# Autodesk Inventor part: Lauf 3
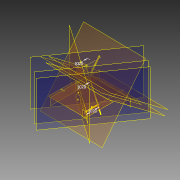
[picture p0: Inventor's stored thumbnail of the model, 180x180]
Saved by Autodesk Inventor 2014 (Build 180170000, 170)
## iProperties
Created: 2013-09
Part Number: Lauf 3
Material: Edelstahl
Document SubType Name: Modeling
Designer: Stefan Tammegger
Mass: 12281.6 g
Surface Area: 15206.1 cm^2
Volume: 1520 cm^3
Density: 8.08 g/cm^3
Appearance: Halbpoliert
Author: Stefan Tammegger
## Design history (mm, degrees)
workplane "Arbeitsebene1"
workplane "Arbeitsebene2"
workplane "Arbeitsebene5"
  workaxis "Arbeitsachse3"
workplane "Arbeitsebene6"
sketch "Skizze2"
  geometry: L1 (1555.396, -769.838)-(1555.396, -948.838) reference; L2 (1272.396, -769.838)-(1555.396, -769.838) reference; L3 (1555.396, -769.838)-(1555.396, 250.162); 2 further points
  constraints: 2 end point, 1 coincident, 1 perpendicular
  dimensions: "d11" = 1020 distance of L1.start L3.end
  node "Referenz2"
  node "Referenz3"
sketch "Skizze3"
  geometry: L1 (70, -835.546)-(120, -835.546); L2 (120, -835.546)-(120, -805.546); L3 (120, -805.546)-(70, -805.546); L4 (70, -805.546)-(70, -835.546); L5 (118, -833.546)-(72, -833.546); L6 (72, -833.546)-(72, -807.546); L7 (72, -807.546)-(118, -807.546); L8 (118, -807.546)-(118, -833.546); L9 (0, 0)-(0, 146.63) reference; L10 (-2841.447, 0)-(2048.984, 0) reference; 2 further points
  constraints: 16 end point, 4 parallel, 2 perpendicular, 1 horizontal, 3 other
  dimensions: "d12" = 50 distance of L1.start L1.end; "d13" = 30 distance of L1.end L2.end; "d14" = 2 distance between parallel lines of L3 L7; "d15" = 70 distance between parallel lines of L9 L4; "d16" = 0 distance from line of L1 point (0, -835.546)
extrude "Extrusion1" new body sketch "Skizze3" distance "d17" = 5000; taper "d18" = 0 deg
workplane "Arbeitsebene8"
sketch "Skizze4"
  geometry: L1 (-1045.237, -70)-(3050.576, -70) reference; L2 (-1045.237, -120)-(3050.576, -120) reference; L3 (-283, 0)-(-283, -500) reference; L4 (0, 0)-(0, -500) reference; L5 (-200, -55)-(-90, -55); L6 (-90, -55)-(-90, -135); L7 (-90, -135)-(-200, -135); L8 (-200, -135)-(-200, -55); C1 r 5.5 at (-185, -95); C2 r 5.5 at (-105, -95); 1 further point
  constraints: 8 end point, 2 centre point, 2 parallel, 1 horizontal, 1 perpendicular
  dimensions: "d19" = 110 distance of L6.end L7.end; "d20" = 80 distance of L7.end L5.start; "d21" = 90 distance between parallel lines of L4 L6; "d22" = 15 distance between parallel lines of L2 L7; "d23" = 11 diameter of C1; "d24" = 11 diameter of C2; "d25" = 15 distance from line of L8 C1.centre; "d26" = 15 distance from line of L6 C2.centre; "d27" = 40 distance from line of L7 C1.centre; "d28" = 40 distance from line of L7 C2.centre
extrude "Extrusion2" new body sketch "Skizze4" distance "d29" = 6; taper "d30" = 0 deg
fillet "Rundung1" dims "d31" = 4
sketch "Skizze5"
  geometry: L1 (90, 131)-(90, 59) reference; L2 (94, 55)-(196, 55) reference; L3 (130, 120)-(160, 120); L4 (160, 120)-(160, 70); L5 (160, 70)-(130, 70); L6 (130, 70)-(130, 120); L7 (158, 118)-(132, 118); L8 (132, 118)-(132, 72); L9 (132, 72)-(158, 72); L10 (158, 72)-(158, 118); 1 further point
  constraints: 16 end point, 4 parallel, 2 perpendicular, 1 horizontal, 3 other
  dimensions: "d32" = 50 distance of L3.end L4.end; "d33" = 30 distance of L3.start L3.end; "d34" = 40 distance between parallel lines of L1 L6; "d35" = 15 distance between parallel lines of L2 L5; "d36" = 2 distance between parallel lines of L6 L8
extrude "Extrusion3" new body sketch "Skizze5" distance "d37" = 1200; taper "d38" = 0 deg
sketch "Skizze6"
  geometry: L1 (5000, -30)-(5000, 0) reference; L2 (5000, 0)-(0, 0) reference; L3 (0, -30)-(0, 0) reference; L4 (5000, -30)-(0, -30) reference; L5 (4561.311, -916.867)-(3873.037, 66.128) reference; L6 (4536.736, -934.074)-(3848.463, 48.922) reference; 3 further points
  constraints: 4 point on line
sketch "Skizze7"
  geometry: L1 (50, 0)-(0, 0) reference; L2 (50, 0)-(50, 1200) reference; L3 (0, 1200)-(50, 1200) reference; L4 (0, 0)-(0, 1200) reference; L5 (0, 499.448)-(50, 499.448) reference; L6 (50, 499.448)-(50, 3367.255) reference; L7 (0, 3367.255)-(50, 3367.255) reference; L8 (0, 499.448)-(0, 3367.255) reference; 2 further points
  constraints: 1 point on line
  node "Projizierte Kontur1"
workplane "Arbeitsebene9"
feature "Trennen1"
feature "Trennen2"
workplane "Arbeitsebene10"
sketch "Skizze8"
  geometry: L1 (0, 0)-(0, -500) reference; L2 (1020, 50.711)-(1020, -500); 1 further point
  constraints: 2 end point, 1 parallel
  dimensions: "d39" = 1020 distance between parallel lines of L1 L2
  node "Referenz7"
workplane "Arbeitsebene13"
  workplane "Arbeitsebene12"
workpoint "Arbeitspunkt1"
workpoint "Arbeitspunkt2"
workplane "Arbeitsebene14"
workpoint "Arbeitspunkt5"
workplane "Arbeitsebene15"
  workpoint "Arbeitspunkt3"
  workpoint "Arbeitspunkt4"
workplane "Arbeitsebene16"
sketch "Skizze11"
  geometry: L1 (0, 0)-(500, 0) reference; L2 (33.807, 1020)-(500, 1020); 1 further point
  constraints: 2 end point, 1 parallel
  dimensions: "d50" = 1020 distance between parallel lines of L1 L2
  node "Referenz8"
workplane "Arbeitsebene17"
  workaxis "Arbeitsachse4"
sketch "Skizze12"
  geometry: L1 (33.807, -831.485)-(500, -831.485) reference; L2 (0, 184.613)-(0, 43.995) reference; L3 (30, -831.485)-(80, -831.485); L4 (80, -831.485)-(80, -801.485); L5 (80, -801.485)-(30, -801.485); L6 (30, -801.485)-(30, -831.485); L7 (32, -803.485)-(78, -803.485); L8 (78, -803.485)-(78, -829.485); L9 (78, -829.485)-(32, -829.485); L10 (32, -829.485)-(32, -803.485); 1 further point
  constraints: 16 end point, 4 parallel, 2 perpendicular, 1 horizontal, 3 other
  dimensions: "d52" = 50 distance of L3.start L3.end; "d53" = 30 distance of L3.end L4.end; "d54" = 0 distance between parallel lines of L1 L3; "d55" = 30 distance between parallel lines of L2 L6; "d56" = 2 distance between parallel lines of L1 L9
extrude "Extrusion5" new body sketch "Skizze12" stored distance "d57" = 2800; taper "d58" = 0 deg
workplane "Arbeitsebene18"
sketch "Skizze13"
  geometry: L1 (17.005, 930.85)-(48.24, -1306.042) reference; L2 (98.235, -1305.344)-(67, 931.548) reference; L3 (-130, -120)-(470, -120) reference; L4 (0, 0)-(448.724, -387.328) reference; L5 (470, -70)-(-130, -70) reference; L6 (81.096, -70)-(-8.904, -70); L7 (-8.904, -70)-(-8.904, -135); L8 (-8.904, -135)-(81.096, -135); L9 (81.096, -135)-(81.096, -70); C1 r 5.5 at (6.096, -102.5); 1 further point
  constraints: 8 end point, 2 parallel, 2 point on line, 1 centre point, 1 horizontal, 1 perpendicular
  dimensions: "d62" = 90 distance of L8.end L7.end; "d63" = 65 distance of L7.end L6.end; "d64" = 11 diameter of C1; "d65" = 15 distance from line of L7 C1.centre; "d66" = 32.5 distance from line of L8 C1.centre
extrude "Extrusion6" new body sketch "Skizze13" distance "d67" = 6; taper "d68" = 0 deg
fillet "Rundung2" dims "d69" = 4
sketch "Skizze14"
  geometry: L1 (-98.235, 1305.344)-(-67, -931.548) reference; L2 (-17.005, -930.85)-(-48.24, 1306.042) reference; L3 (130, 120)-(-470, 120) reference; L4 (-470, 70)-(130, 70) reference; L5 (-31.679, 120)-(-30.98, 70.005); L6 (-30.98, 70.005)-(-80.976, 69.307); L7 (-80.976, 69.307)-(-81.674, 119.302); L8 (-81.674, 119.302)-(-31.679, 120); L9 (-33.65, 117.972)-(-33.008, 71.977); L10 (-33.008, 71.977)-(-79.004, 71.334); L11 (-79.004, 71.334)-(-79.646, 117.33); L12 (-79.646, 117.33)-(-33.65, 117.972); 1 further point
  constraints: 16 end point, 5 point on line, 3 other
  dimensions: "d70" = 50 distance of L5.start L5.end; "d71" = 50 distance of L5.end L6.end; "d72" = 50 distance of L6.end L7.end; "d73" = 2 distance between parallel lines of L8 L12
extrude "Extrusion7" new body sketch "Skizze14" distance "d74" = 1500; taper "d75" = 0 deg
sketch "Skizze15"
  geometry: L1 (0, 0)-(-50, 0) reference; L2 (0, 0)-(0, 1500) reference; L3 (-50, 1500)-(0, 1500) reference; L4 (-50, 0)-(-50, 1500) reference; L5 (-1236.158, 344.407)-(1000.952, 2028.253) reference; L6 (-1218.116, 320.438)-(1018.994, 2004.284) reference; 3 further points
  constraints: 4 point on line
sketch "Skizze16"
  geometry: L1 (0, 0)-(-50, 0) reference; L2 (0, 0)-(0, 1500) reference; L3 (-50, 1500)-(0, 1500) reference; L4 (-50, 0)-(-50, 1500) reference; L5 (-1050.952, 2028.253)-(1186.158, 344.407) reference; 2 further points
  constraints: 2 point on line
workplane "Arbeitsebene19"
feature "Trennen5"
feature "Trennen6"
workplane "Arbeitsebene20"
feature "Trennen7"
workplane "Arbeitsebene21"
sketch "Skizze17"
  geometry: L1 (27.854, 153.926)-(42.527, -896.924) reference; L2 (92.522, -896.226)-(77.849, 154.624) reference; L3 (0, 0)-(499.951, 6.981) reference; L4 (3.63, -259.975)-(0, 0) reference; L5 (15.308, -21.985)-(16.565, -111.976); L6 (16.565, -111.976)-(96.557, -110.859); L7 (96.557, -110.859)-(95.301, -20.868); L8 (95.301, -20.868)-(15.308, -21.985); C1 r 5.5 at (56.352, -96.419); 1 further point
  constraints: 8 end point, 2 parallel, 1 centre point, 1 perpendicular
  dimensions: "d77" = 90 distance of L5.start L5.end; "d78" = 80 distance of L5.end L6.end; "d80" = 90 distance of L6.end L7.end; "d81" = 15 distance between parallel lines of L7 L2; "d82" = 11 diameter of C1; "d83" = 15 distance from line of C1.centre L6; "d84" = 40 distance from line of L5 C1.centre
extrude "Extrusion8" new body sketch "Skizze17" distance "d85" = 6; taper "d86" = 0 deg
sketch "Skizze18"
  geometry: L1 (-95.301, 20.868)-(-15.308, 21.985) reference; L2 (-92.522, 896.226)-(-77.849, -154.624) reference; L3 (-27.854, -153.926)-(-42.527, 896.924) reference; L4 (-80.302, 21.077)-(-30.307, 21.775); L5 (-30.307, 21.775)-(-30.726, 51.772); L6 (-30.726, 51.772)-(-80.721, 51.074); L7 (-80.721, 51.074)-(-80.302, 21.077); L8 (-78.33, 23.105)-(-32.335, 23.747); L9 (-32.335, 23.747)-(-32.698, 49.745); L10 (-32.698, 49.745)-(-78.693, 49.102); L11 (-78.693, 49.102)-(-78.33, 23.105); 1 further point
  constraints: 16 end point, 5 point on line, 2 perpendicular, 3 other
  dimensions: "d87" = 30 distance of L4.end L5.end; "d88" = 50 distance of L5.end L6.end; "d89" = 2 distance between parallel lines of L10 L6
extrude "Extrusion9" new body sketch "Skizze18" distance "d90" = 1500; taper "d91" = 0 deg
sketch "Skizze19"
  geometry: L1 (-1315.388, 30)-(-1275.387, 0) reference; L2 (-1275.387, 0)-(0, 0) reference; L3 (0, 30)-(0, 0) reference; L4 (-1315.388, 30)-(0, 30) reference; L5 (-961.334, -905.121)-(-59.274, 293.331) reference; L6 (-937.365, -923.162)-(-35.305, 275.289) reference; 3 further points
  constraints: 4 point on line
sketch "Skizze20"
  geometry: L1 (1275.387, 0)-(1315.388, 30) reference; L2 (0, 30)-(1315.388, 30) reference; L3 (0, 0)-(0, 30) reference; L4 (1275.387, 0)-(0, 0) reference; L5 (961.334, -905.121)-(59.274, 293.331) reference; 2 further points
  constraints: 2 point on line
workplane "Arbeitsebene22"
feature "Trennen8"
feature "Trennen9"
workplane "Arbeitsebene23"
sketch "Skizze21"
  geometry: L1 (-1561, -70)-(968.98, -70) reference; L2 (-1560.99, -120)-(969.679, -120) reference; L3 (-277, 0)-(-277, -500) reference; L4 (0, 0)-(0, -500) reference; L5 (-190, -55)-(-80, -55); L6 (-80, -55)-(-80, -135); L7 (-80, -135)-(-190, -135); L8 (-190, -135)-(-190, -55); C1 r 5.5 at (-175, -95); C2 r 5.5 at (-95, -95); 1 further point
  constraints: 8 end point, 2 centre point, 2 parallel, 1 horizontal, 1 perpendicular
  dimensions: "d92" = 110 distance of L5.start L5.end; "d93" = 80 distance of L5.end L6.end; "d94" = 15 distance between parallel lines of L1 L5; "d95" = 80 distance between parallel lines of L4 L6; "d96" = 11 diameter of C1; "d97" = 11 diameter of C2; "d98" = 15 distance from line of L8 C1.centre; "d99" = 15 distance from line of L6 C2.centre; "d100" = 40 distance from line of L7 C1.centre; "d101" = 40 distance from line of L7 C2.centre
extrude "Extrusion10" new body sketch "Skizze21" distance "d102" = 6; taper "d103" = 0 deg
fillet "Rundung3" dims "d104" = 4
sketch "Skizze22"
  geometry: L1 (190, 59)-(190, 131) reference; L2 (1560.99, 120)-(-969.679, 120) reference; L3 (1561, 70)-(-968.98, 70) reference; L4 (120, 120)-(150, 120); L5 (150, 120)-(150, 70); L6 (150, 70)-(120, 70); L7 (120, 70)-(120, 120); L8 (148, 118)-(122, 118); L9 (122, 118)-(122, 72); L10 (122, 72)-(148, 72); L11 (148, 72)-(148, 118); 1 further point
  constraints: 16 end point, 4 parallel, 2 perpendicular, 2 point on line, 1 horizontal, 3 other
  dimensions: "d105" = 30 distance of L5.end L6.end; "d106" = 40 distance between parallel lines of L1 L5; "d107" = 2 distance between parallel lines of L5 L11
extrude "Extrusion11" new body sketch "Skizze22" stored distance "d108" = 6; taper "d109" = 0 deg
workplane "Arbeitsebene25"
  workplane "Arbeitsebene24"
workplane "Arbeitsebene26"
workplane "Arbeitsebene27"
sketch "Skizze23"
  geometry: L1 (35.482, 30)-(85.482, 30) reference; L2 (-2877.121, 835.546)-(2015.564, 835.546) reference; L3 (35.311, 1005.299)-(35.482, 30) reference; C1 r 6 at (60.448, 225); C2 r 6 at (60.414, 420); C3 r 6 at (60.38, 615); C4 r 6 at (60.345, 810); 1 further point
  constraints: 4 centre point
  dimensions: "d113" = 12 diameter of C1; "d114" = 12 diameter of C2; "d115" = 12 diameter of C3; "d116" = 12 diameter of C4; "d117" = 195 distance from line of C1.centre L1; "d119" = 195 distance of C4.centre C3.centre; "d120" = 195 distance of C3.centre C2.centre; "d121" = 195 distance of C2.centre C1.centre; "d122" = 25 distance from line of L3 C1.centre; "d123" = 25 distance from line of L3 C2.centre; "d124" = 25 distance from line of L3 C3.centre; "d125" = 25 distance from line of L3 C4.centre
extrude "Extrusion12" new body sketch "Skizze23" stored distance "d126" = 6; taper "d127" = 0 deg
sketch "Skizze24"
  geometry: L1 (35.825, 30)-(85.825, 30) reference; C1 r 6 at (60.825, 225); C2 r 6 at (60.825, 420); C3 r 6 at (60.825, 615); C4 r 6 at (60.825, 810); 1 further point
  constraints: 4 centre point
  dimensions: "d128" = 12 diameter of C1; "d129" = 195 distance from line of L1 C1.centre; "d130" = 25 horizontal distance of C1.centre L1.start; "d131" = 12 diameter of C2; "d132" = 12 diameter of C3; "d133" = 12 diameter of C4; "d134" = 195 distance of C2.centre C1.centre; "d135" = 195 distance of C3.centre C2.centre; "d136" = 195 distance of C4.centre C3.centre
extrude "Extrusion13" new body sketch "Skizze24" stored distance "d137" = 6; taper "d138" = 0 deg
workplane "Arbeitsebene30"
  workplane "Arbeitsebene29"
sketch "Skizze25"
  geometry: L1 (1362.718, -801.485)-(1312.718, -801.485) reference; L2 (1362.718, 103.636)-(1362.718, -801.485) reference; C1 r 6 at (1337.718, -612.485); C2 r 6 at (1337.718, -417.485); C3 r 6 at (1337.718, -222.485); C4 r 6 at (1337.718, -27.485); 1 further point
  constraints: 4 centre point
  dimensions: "d141" = 12 diameter of C1; "d142" = 12 diameter of C2; "d143" = 12 diameter of C3; "d144" = 12 diameter of C4; "d145" = 189 distance from line of C1.centre L1; "d146" = 195 distance of C2.centre C1.centre; "d147" = 195 distance of C3.centre C2.centre; "d149" = 195 distance of C4.centre C3.centre; "d152" = 25 distance from line of L2 C1.centre; "d153" = 25 distance from line of L2 C2.centre; "d154" = 25 distance from line of L2 C3.centre; "d155" = 25 distance from line of L2 C4.centre
extrude "Extrusion15" new body sketch "Skizze25" stored distance "d156" = 6; taper "d157" = 0 deg
node "Volumenkörper1"
node "Referenz4"
node "Referenz5"
node "Referenz6"
node "Volumenkörper2"
node "Volumenkörper3"
workplane "Arbeitsebene11"
node "Referenz9"
node "Volumenkörper5"
node "Referenz10"
node "Volumenkörper6"
node "Volumenkörper7"
node "Referenz11"
node "Referenz12"
node "Volumenkörper8"
node "Volumenkörper9"
node "Referenz13"
node "Referenz14"
node "Volumenkörper10"
node "Volumenkörper11"
workpoint "Arbeitspunkt6"
node "Volumenkörper12"
node "Volumenkörper13"
workplane "Arbeitsebene28"
workaxis "Arbeitsachse5"
node "Volumenkörper15"
other parameters: "d2" = 90 deg, "d40" = 0, "d41" = 90 deg, "d51" = 90 deg, "d76" = 0, "d110" = 90 deg, "d111" = 678, "d112" = 2240.75, "d139" = 90 deg, "d140" = 425.75
